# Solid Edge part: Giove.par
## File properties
Title: Giove ø 37 cm
Author: DESYS
Template: Normal.par
Last saved by: s.pallini
Revision: 9
Application: Solid Edge
Tipo di contenuto documento: 0
Precisione: 0,990
Document Number: 8034
Revision: 0
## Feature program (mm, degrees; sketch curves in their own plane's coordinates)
sketch for "ExtrudedProtrusion_1" plane through (0, 0, 0) normal (0, -1, 0) x-axis (1, 0, 0)
  circle centre (0, 0) radius 185
extrude "ExtrudedProtrusion_1" add finite 150 along +normal  Treatment1_DraftAngle = 3 deg
sketch for "ExtrudedCutout_2" plane through (0, 0, 0) normal (0, 1, 0) x-axis (-1, 0, 0)
  circle centre (0, 0) radius 150
extrude "ExtrudedCutout_2" cut finite 120 along -normal
fillet "Rotondo_1" radius 100
thinwall "Thinwall_1"  Thickness = 10 mm
sketch for "unnamed Protrusion 1" #1 plane through (0, -150, 0) normal (0, -1, 0) x-axis (0, 0, 1)
  circle centre (0, 0) radius 177.1388
sketch for "unnamed Protrusion 1" #2 plane through (0, -150, 0) normal (0, -1, 0) x-axis (0, 0, 1)
  circle centre (0, 0) radius 137.1388
sketch for "unnamed Protrusion 1" #3 plane through (0, -150, 0) normal (0, -1, 0) x-axis (0, 0, 1)
  circle centre (0, 0) radius 35
extrude "unnamed Protrusion 1" add along +normal
sketch for "Foro_2" plane through (0, -150, 0) normal (0, -1, 0) x-axis (0, 0, 1)
  hole centre (0, 0) bore radius 25
hole "Foro_2" diameter 50 through
sketch for "Foro_3" plane through (0, -150, 0) normal (0, -1, 0) x-axis (1, 0, 0)
  hole centre (-157.1388, 0) bore radius 7.5
hole "Foro_3" diameter 15 finite
sketch for "Foro_4" plane through (0, -150, 0) normal (0, -1, 0) x-axis (1, 0, 0)
  hole centre (157.1388, 0) bore radius 5
hole "Foro_4" diameter 10 finite
fillet "Rotondo_2" radius 10
fillet "Rotondo_3" radius 5
fillet "Rotondo_4" radius 5
fillet "Rotondo_5" radius 10
fillet "Rotondo_6" radius 15
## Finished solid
Body 1: solid body, 24 faces, 24 edges, 0 vertices.
  Faces by surface: torus 10, plane 7, cylinder 6, cone 1
  Edges by curve: circle 24
Bounding box of the edges (mm; curved faces can reach further): 368.897 x 150.000 x 368.897, from (-184.4485, -150, -184.4485) to (184.4485, 0, 184.4485).
Cylindrical faces by radius (mm): R5 x1, R7.5 x1, R25 x1, R35 x1, R137.1388 x1, R150 x1
Conical faces (half-angle, radius in mm at the cone's reference point): 3 deg R185 x1
Toroidal faces (ring radius, tube radius in mm): R30 r5 x1, R40 r15 x1, R45 r10 x1, R50 r100 x1, R50 r110 x1, R132.1388 r5 x1, R147.1388 r10 x1, R160 r10 x1, R172.394 r5 x1, R174.4622 r10 x1
Planar faces by outward normal: +y 2, -y 5
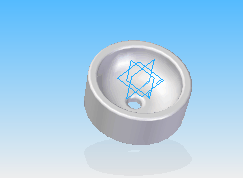
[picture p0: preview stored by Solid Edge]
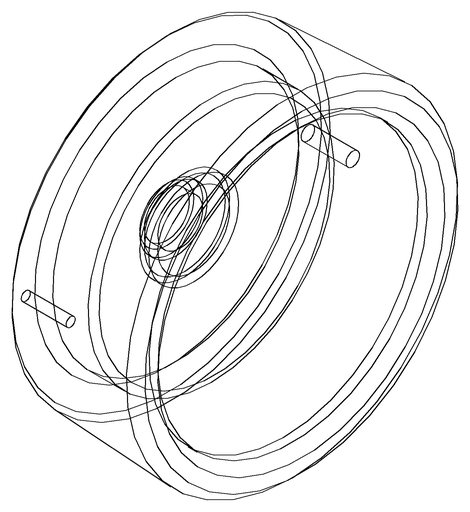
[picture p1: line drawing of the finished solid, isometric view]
